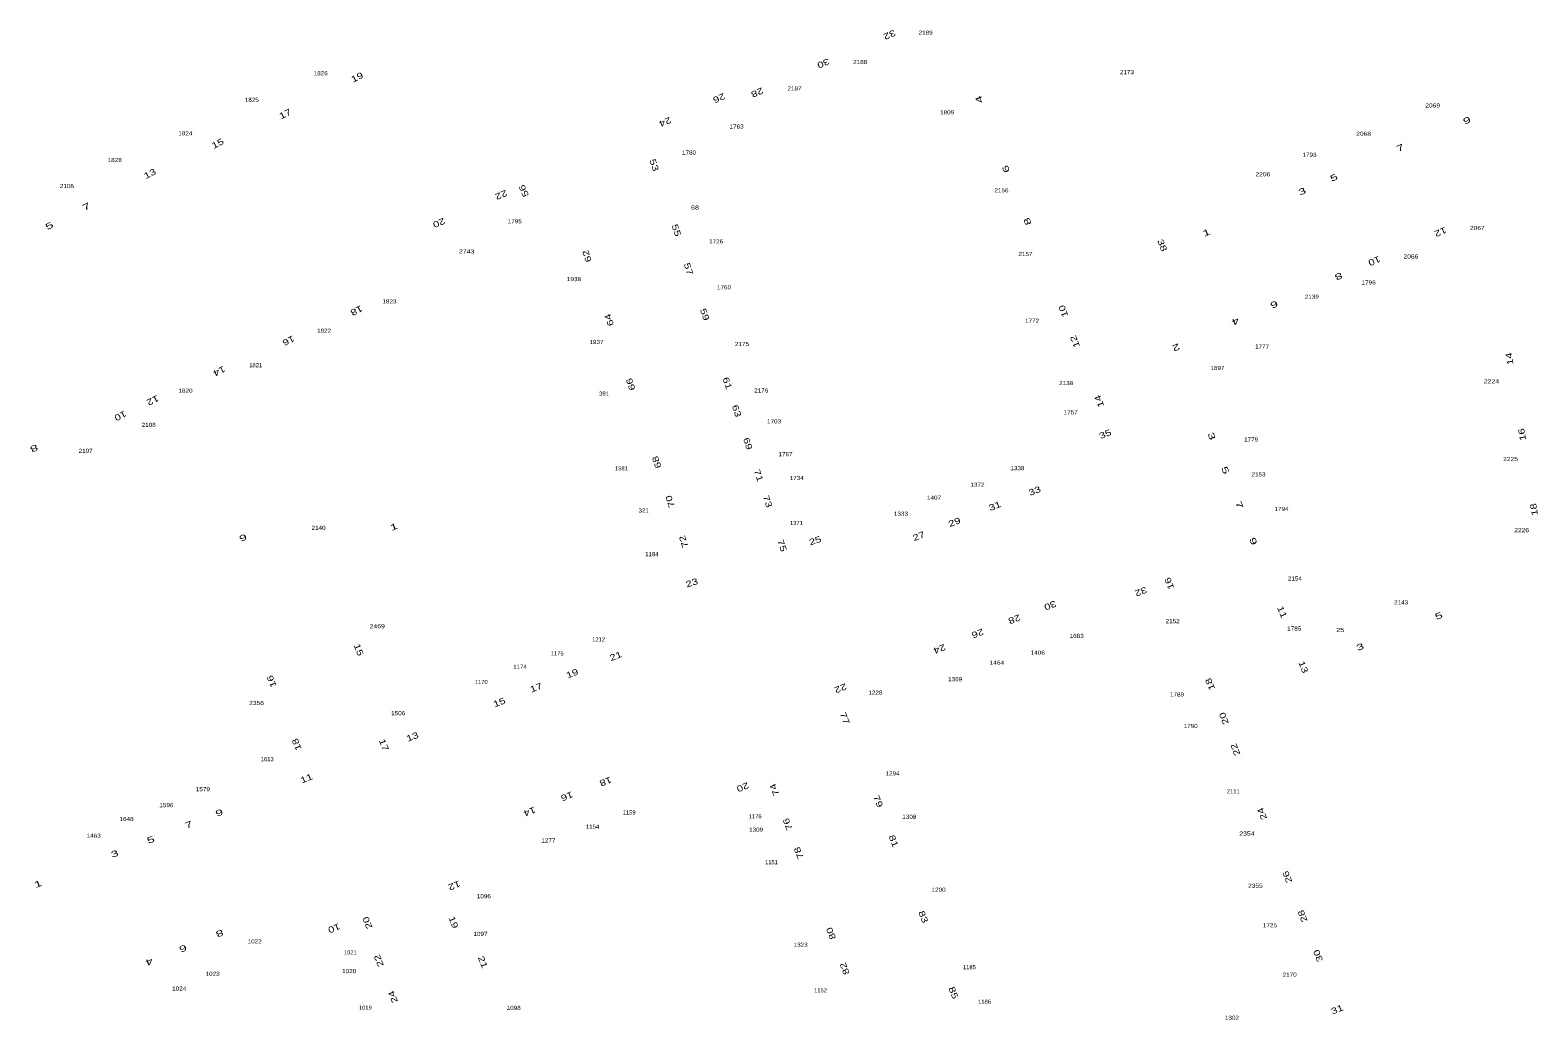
# Model space of a CAD drawing. Extents: x -828673 to -815583, y -1077737 to -1063807.
# Drawn here: x -821440 to -821074.1, y -1071844.9 to -1071604.8 of the extents above; entities that cross this region are included whole.
import ezdxf
from ezdxf.enums import TextEntityAlignment as Align

# ---------------------------------------------------------------- set-up
doc = ezdxf.new("R2010")
doc.units = 0
doc.header["$LTSCALE"] = 0.4
doc.layers.add('1', color=7, linetype='Continuous')
doc.layers.add('2', color=7, linetype='Continuous')

msp = doc.modelspace()

# ---------------------------------------------------------------- texts
at = {"layer": '1'}
for s, width, p in [('2189', 1.15, (-821222.729, -1071605.887)), ('2188', 1.15, (-821238.591, -1071613.005)), ('1826', 1.15, (-821369.518, -1071615.734)), ('2173', 1.15, (-821173.859, -1071615.469)), ('2187', 1.15, (-821254.536, -1071619.411)), ('1825', 1.15, (-821386.233, -1071622.171)), ('2069', 1.2, (-821099.682, -1071623.547)), ('1809', 1.15, (-821217.498, -1071625.231)), ('1824', 1.15, (-821402.364, -1071630.3)), ('1763', 1.15, (-821268.577, -1071628.664)), ('2068', 1.2, (-821116.425, -1071630.407)), ('1780', 1.15, (-821280.124, -1071634.961)), ('1828', 1.15, (-821419.504, -1071636.788)), ('1793', 1.15, (-821129.555, -1071635.512)), ('2206', 1.2, (-821140.877, -1071640.245)), ('2106', 1.15, (-821431.11, -1071643.099)), ('2156', 1.15, (-821204.317, -1071644.134)), ('68', 1.3, (-821278.674, -1071648.318)), ('1795', 1.15, (-821322.429, -1071651.647)), ('2067', 1.2, (-821088.837, -1071653.274)), ('1726', 1.15, (-821273.556, -1071656.53)), ('2743', 1.25, (-821334.095, -1071658.955)), ('2157', 1.15, (-821198.479, -1071659.573)), ('2066', 1.2, (-821104.944, -1071660.188)), ('1938', 1.15, (-821308.064, -1071665.676)), ('1760', 1.15, (-821271.63, -1071667.667)), ('1796', 1.15, (-821115.203, -1071666.516)), ('1823', 1.15, (-821352.833, -1071671.084)), ('2139', 1.15, (-821129.002, -1071669.948)), ('1822', 1.15, (-821368.693, -1071678.184)), ('1772', 1.15, (-821196.894, -1071675.784)), ('1937', 1.15, (-821302.597, -1071680.92)), ('2175', 1.15, (-821267.281, -1071681.424)), ('1777', 1.15, (-821141.068, -1071682.02)), ('1821', 1.05, (-821385.281, -1071686.567)), ('1697', 1.15, (-821151.912, -1071687.232)), ('1820', 1.15, (-821402.312, -1071692.75)), ('391', 1.1, (-821300.758, -1071693.452)), ('2176', 1.15, (-821262.596, -1071692.71)), ('2138', 1.15, (-821188.608, -1071690.899)), ('2224', 1.25, (-821085.404, -1071690.477)), ('2108', 1.15, (-821411.247, -1071701.048)), ('1703', 1.15, (-821259.499, -1071700.205)), ('1757', 1.15, (-821187.521, -1071697.986)), ('1779', 1.15, (-821143.731, -1071704.588)), ('2107', 1.15, (-821426.552, -1071707.335)), ('1767', 1.15, (-821256.71, -1071708.148)), ('1581', 1.05, (-821296.534, -1071711.586)), ('1338', 1.15, (-821200.453, -1071711.552)), ('2225', 1.2, (-821080.765, -1071709.322)), ('1734', 1.15, (-821253.99, -1071713.926)), ('1372', 1.15, (-821210.131, -1071715.559)), ('2153', 1.15, (-821141.924, -1071713.044)), ('1407', 1.15, (-821220.677, -1071718.699)), ('321', 1.1, (-821291.147, -1071721.809)), ('1333', 1.15, (-821228.712, -1071722.593)), ('1794', 1.15, (-821136.343, -1071721.447)), ('2140', 1.15, (-821370.03, -1071726.031)), ('1371', 1.05, (-821254.074, -1071724.854)), ('2226', 1.2, (-821078.074, -1071726.589)), ('1184', 1.1, (-821289.138, -1071732.416)), ('2154', 1.15, (-821133.1, -1071738.318)), ('2143', 1.15, (-821107.32, -1071744.115)), ('2152', 1.15, (-821162.771, -1071748.661)), ('2469', 1.25, (-821355.793, -1071749.908)), ('1683', 1.15, (-821186.061, -1071752.238)), ('1785', 1.15, (-821133.26, -1071750.444)), ('25', 1.3, (-821122.104, -1071750.816)), ('1212', 1.05, (-821302.074, -1071753.08)), ('1174', 1.1, (-821321.141, -1071759.71)), ('1175', 1.05, (-821312.121, -1071756.502)), ('1464', 1.2, (-821205.434, -1071758.728)), ('1406', 1.15, (-821195.501, -1071756.311)), ('1170', 1.05, (-821330.547, -1071763.431)), ('1369', 1.15, (-821215.544, -1071762.757)), ('1228', 1.15, (-821234.901, -1071766.003)), ('1789', 1.15, (-821161.704, -1071766.451)), ('2358', 1.2, (-821385.088, -1071768.513)), ('1506', 1.15, (-821350.705, -1071770.995)), ('1790', 1.15, (-821158.393, -1071774.105)), ('1613', 1.05, (-821382.494, -1071782.15)), ('1294', 1.15, (-821230.74, -1071785.609)), ('1579', 1.15, (-821398.111, -1071789.429)), ('1596', 1.15, (-821406.964, -1071793.304)), ('1159', 1.05, (-821294.657, -1071795.084)), ('1176', 1.05, (-821264.097, -1071796.027)), ('1308', 1.15, (-821226.674, -1071796.136)), ('1648', 1.15, (-821416.615, -1071796.665)), ('1154', 1.1, (-821303.542, -1071798.545)), ('1309', 1.15, (-821263.846, -1071799.25)), ('1463', 1.15, (-821424.603, -1071800.704)), ('1277', 1.15, (-821314.264, -1071801.879)), ('2354', 1.25, (-821144.749, -1071800.206)), ('1200', 1.15, (-821219.56, -1071813.817)), ('2355', 1.2, (-821142.691, -1071812.873)), ('1096', 1.15, (-821329.937, -1071815.398)), ('1097', 1.15, (-821330.749, -1071824.544)), ('1725', 1.15, (-821139.157, -1071822.452)), ('1022', 1.15, (-821385.527, -1071826.347)), ('1021', 1.05, (-821362.346, -1071829.039)), ('1323', 1.15, (-821253.038, -1071827.159)), ('1185', 1.05, (-821212.097, -1071832.621)), ('1023', 1.15, (-821395.752, -1071834.216)), ('1020', 1.15, (-821362.609, -1071833.575)), ('2170', 1.15, (-821134.37, -1071834.427)), ('1024', 1.15, (-821403.843, -1071837.807)), ('1152', 1.05, (-821248.218, -1071838.234)), ('1019', 1.05, (-821358.676, -1071842.438)), ('1098', 1.15, (-821322.681, -1071842.501)), ('1186', 1.05, (-821208.428, -1071840.991)), ('1302', 1.15, (-821148.373, -1071844.888))]:
    msp.add_text(s, height=1, dxfattribs=dict(at, width=width)).set_placement(p, align=Align.CENTER)
for s, p in [('2111', (-821148.058, -1071789.951)), ('1151', (-821260.129, -1071807.157))]:
    msp.add_text(s, height=1, dxfattribs=at).set_placement(p, align=Align.CENTER)
at = {"layer": '2'}
for s, rotation, width, p in [('32', 203.639, 1.35, (-821231.7593, -1071605.2158)), ('30', 203.768, 1.35, (-821247.8297, -1071612.1668)), ('19', 27.044, 1.35, (-821360.3275, -1071616.8746)), ('28', 203.763, 1.35, (-821263.8778, -1071619.2327)), ('26', 203.789, 1.35, (-821273.1455, -1071620.5883)), ('4', 111.683, 1.65, (-821209.0423, -1071621.3411)), ('17', 27.055, 1.35, (-821377.8006, -1071625.7723)), ('24', 203.123, 1.35, (-821286.2015, -1071626.3637)), ('9', 23.143, 1.65, (-821091.0823, -1071627.3578)), ('15', 27.027, 1.35, (-821394.1653, -1071632.943)), ('7', 23.083, 1.65, (-821107.2406, -1071634.0066)), ('53', 288.592, 1.35, (-821289.284, -1071637.7359)), ('6', 111.68, 1.65, (-821202.5332, -1071638.2011)), ('13', 27.099, 1.35, (-821410.6301, -1071640.2632)), ('5', 23.683, 1.65, (-821123.3478, -1071641.2342)), ('22', 204.084, 1.35, (-821325.9819, -1071644.0647)), ('56', 113.931, 1.35, (-821319.5521, -1071643.4742)), ('3', 23.715, 1.65, (-821131.0546, -1071644.5846)), ('7', 27.118, 1.7, (-821426.0364, -1071648.256)), ('5', 27.566, 1.7, (-821435.0196, -1071652.9078)), ('20', 203.602, 1.35, (-821341.0902, -1071650.8497)), ('55', 288.706, 1.35, (-821283.8852, -1071653.563)), ('8', 111.783, 1.65, (-821197.3047, -1071650.9088)), ('12', 203.741, 1.35, (-821098.0495, -1071653.0664)), ('38', 292.612, 1.35, (-821165.9819, -1071657.2711)), ('1', 22.413, 1.65, (-821154.2875, -1071654.5932)), ('62', 108.653, 1.35, (-821304.1824, -1071659.3669)), ('10', 203.719, 1.35, (-821114.1023, -1071660.0857)), ('57', 288.397, 1.35, (-821280.9581, -1071662.9448)), ('8', 203.86, 1.65, (-821122.7916, -1071663.8267)), ('6', 203.732, 1.65, (-821138.4507, -1071670.6614)), ('18', 206.968, 1.35, (-821361.1414, -1071672.1436)), ('64', 108.69, 1.35, (-821298.8005, -1071674.8648)), ('59', 288.751, 1.35, (-821277.0221, -1071673.9984)), ('10', 111.239, 1.35, (-821188.5916, -1071672.6897)), ('4', 203.378, 1.65, (-821147.8069, -1071674.753)), ('16', 206.96, 1.35, (-821377.6435, -1071679.4574)), ('12', 111.587, 1.35, (-821185.7903, -1071680.0584)), ('2', 203.184, 1.65, (-821162.2117, -1071681.0809)), ('14', 99.106, 1.35, (-821080.29, -1071684.3967)), ('14', 206.847, 1.35, (-821394.4443, -1071686.8555)), ('66', 108.15, 1.35, (-821293.5826, -1071690.4776)), ('61', 288.644, 1.35, (-821271.5388, -1071690.6692)), ('12', 206.468, 1.35, (-821410.5797, -1071693.9335)), ('63', 288.666, 1.35, (-821269.2813, -1071697.385)), ('14', 111.272, 1.35, (-821179.8886, -1071694.5556)), ('10', 207.22, 1.35, (-821418.4439, -1071697.7049)), ('69', 288.435, 1.35, (-821266.5631, -1071705.3418)), ('35', 21.296, 1.35, (-821178.8659, -1071703.4839)), ('3', 291.634, 1.65, (-821153.9795, -1071703.549)), ('16', 99.474, 1.35, (-821077.2306, -1071702.7764)), ('8', 206.469, 1.7, (-821439.3997, -1071705.5701)), ('68', 108.435, 1.35, (-821287.2639, -1071709.3812)), ('5', 291.682, 1.65, (-821150.6887, -1071711.8099)), ('71', 288.653, 1.35, (-821263.9456, -1071713.0471)), ('70', 109.125, 1.35, (-821284.0124, -1071718.8942)), ('73', 288.459, 1.35, (-821261.7685, -1071719.3385)), ('33', 21.448, 1.35, (-821195.9832, -1071717.2601)), ('31', 21.565, 1.35, (-821205.6352, -1071720.9222)), ('7', 291.66, 1.65, (-821147.2862, -1071720.2127)), ('18', 99.098, 1.35, (-821074.3508, -1071720.9716)), ('1', 21.584, 1.65, (-821351.4914, -1071725.9552)), ('29', 21.644, 1.35, (-821215.4336, -1071724.8341)), ('6', 201.956, 1.65, (-821388.6416, -1071727.2396)), ('72', 108.422, 1.35, (-821280.7175, -1071728.6465)), ('75', 288.905, 1.35, (-821258.2511, -1071730.0575)), ('25', 18.683, 1.35, (-821249.2903, -1071729.3299)), ('27', 21.415, 1.35, (-821224.0953, -1071728.2267)), ('9', 291.388, 1.65, (-821143.8863, -1071729.0415)), ('23', 18.53, 1.35, (-821279.2139, -1071739.5566)), ('32', 201.546, 1.35, (-821170.7506, -1071740.3136)), ('16', 111.549, 1.35, (-821162.8784, -1071738.763)), ('30', 201.545, 1.35, (-821192.7436, -1071743.6666)), ('28', 201.383, 1.35, (-821201.4446, -1071747.0143)), ('11', 291.99, 1.35, (-821136.8966, -1071746.2312)), ('5', 21.542, 1.65, (-821097.9204, -1071747.5679)), ('26', 201.107, 1.35, (-821210.3489, -1071750.4595)), ('15', 291.3, 1.35, (-821360.9848, -1071755.3681)), ('24', 201.934, 1.35, (-821219.6088, -1071754.2241)), ('3', 21.75, 1.65, (-821117.0034, -1071755.1167)), ('21', 21.304, 1.35, (-821297.6425, -1071757.3335)), ('13', 291.329, 1.35, (-821131.7369, -1071759.5572)), ('16', 111.03, 1.35, (-821380.7255, -1071762.5206)), ('19', 21.678, 1.35, (-821308.203, -1071761.5653)), ('18', 112.419, 1.35, (-821153.0043, -1071763.18)), ('17', 21.578, 1.35, (-821316.9663, -1071764.9869)), ('22', 201.725, 1.35, (-821243.6189, -1071763.78)), ('15', 21.517, 1.35, (-821325.9016, -1071768.5803)), ('77', 291.493, 1.35, (-821243.0299, -1071771.9947)), ('20', 111.007, 1.35, (-821149.6349, -1071771.5154)), ('18', 111.667, 1.35, (-821374.6474, -1071777.8189)), ('17', 291.749, 1.35, (-821354.8675, -1071778.4646)), ('13', 21.149, 1.35, (-821347.0006, -1071776.9186)), ('22', 111.801, 1.35, (-821146.8648, -1071779.035)), ('11', 22.214, 1.35, (-821372.6955, -1071787.0039)), ('18', 201.566, 1.35, (-821300.6228, -1071786.3908)), ('20', 201.69, 1.35, (-821267.3488, -1071787.764)), ('74', 111.549, 1.35, (-821258.6895, -1071788.808)), ('16', 201.664, 1.35, (-821310.0211, -1071789.9823)), ('79', 291.636, 1.35, (-821234.9313, -1071792.1365)), ('9', 21.379, 1.65, (-821393.8644, -1071795.3544)), ('14', 201.689, 1.35, (-821319.0768, -1071793.6999)), ('24', 111.827, 1.35, (-821140.3806, -1071794.6169)), ('7', 21.856, 1.65, (-821401.2697, -1071798.2469)), ('76', 111.445, 1.35, (-821255.4908, -1071797.1932)), ('5', 21.779, 1.65, (-821410.4828, -1071801.9013)), ('81', 291.594, 1.35, (-821231.1743, -1071801.783)), ('3', 21.257, 1.65, (-821419.2494, -1071805.3106)), ('78', 111.951, 1.35, (-821252.8027, -1071804.1599)), ('26', 111.801, 1.35, (-821134.2508, -1071809.97)), ('1', 21.217, 1.65, (-821437.8269, -1071812.6301)), ('12', 201.584, 1.35, (-821337.3556, -1071811.6193)), ('20', 111.948, 1.35, (-821357.4836, -1071821.0738)), ('19', 291.435, 1.35, (-821337.9852, -1071821.4954)), ('83', 291.397, 1.35, (-821223.9763, -1071820.1664)), ('28', 111.404, 1.35, (-821130.5358, -1071819.4607)), ('8', 201.668, 1.65, (-821394.3041, -1071823.2401)), ('10', 202.598, 1.35, (-821366.5263, -1071821.9967)), ('80', 112.237, 1.35, (-821244.9868, -1071823.6483)), ('6', 202.328, 1.65, (-821403.2026, -1071826.8893)), ('30', 111.59, 1.35, (-821126.7866, -1071829.085)), ('4', 201.189, 1.65, (-821411.3794, -1071830.1416)), ('22', 111.288, 1.35, (-821354.7219, -1071830.2898)), ('21', 291.801, 1.35, (-821330.8482, -1071831.152)), ('82', 111.475, 1.35, (-821241.6577, -1071832.2021)), ('24', 111.351, 1.35, (-821351.2864, -1071839.0696)), ('85', 291.335, 1.35, (-821216.648, -1071838.6116)), ('31', 21.91, 1.35, (-821122.5759, -1071843.0675))]:
    msp.add_text(s, height=1.5, rotation=rotation, dxfattribs=dict(at, width=width)).set_placement(p, align=Align.CENTER)

doc.saveas('drawing.dxf')
